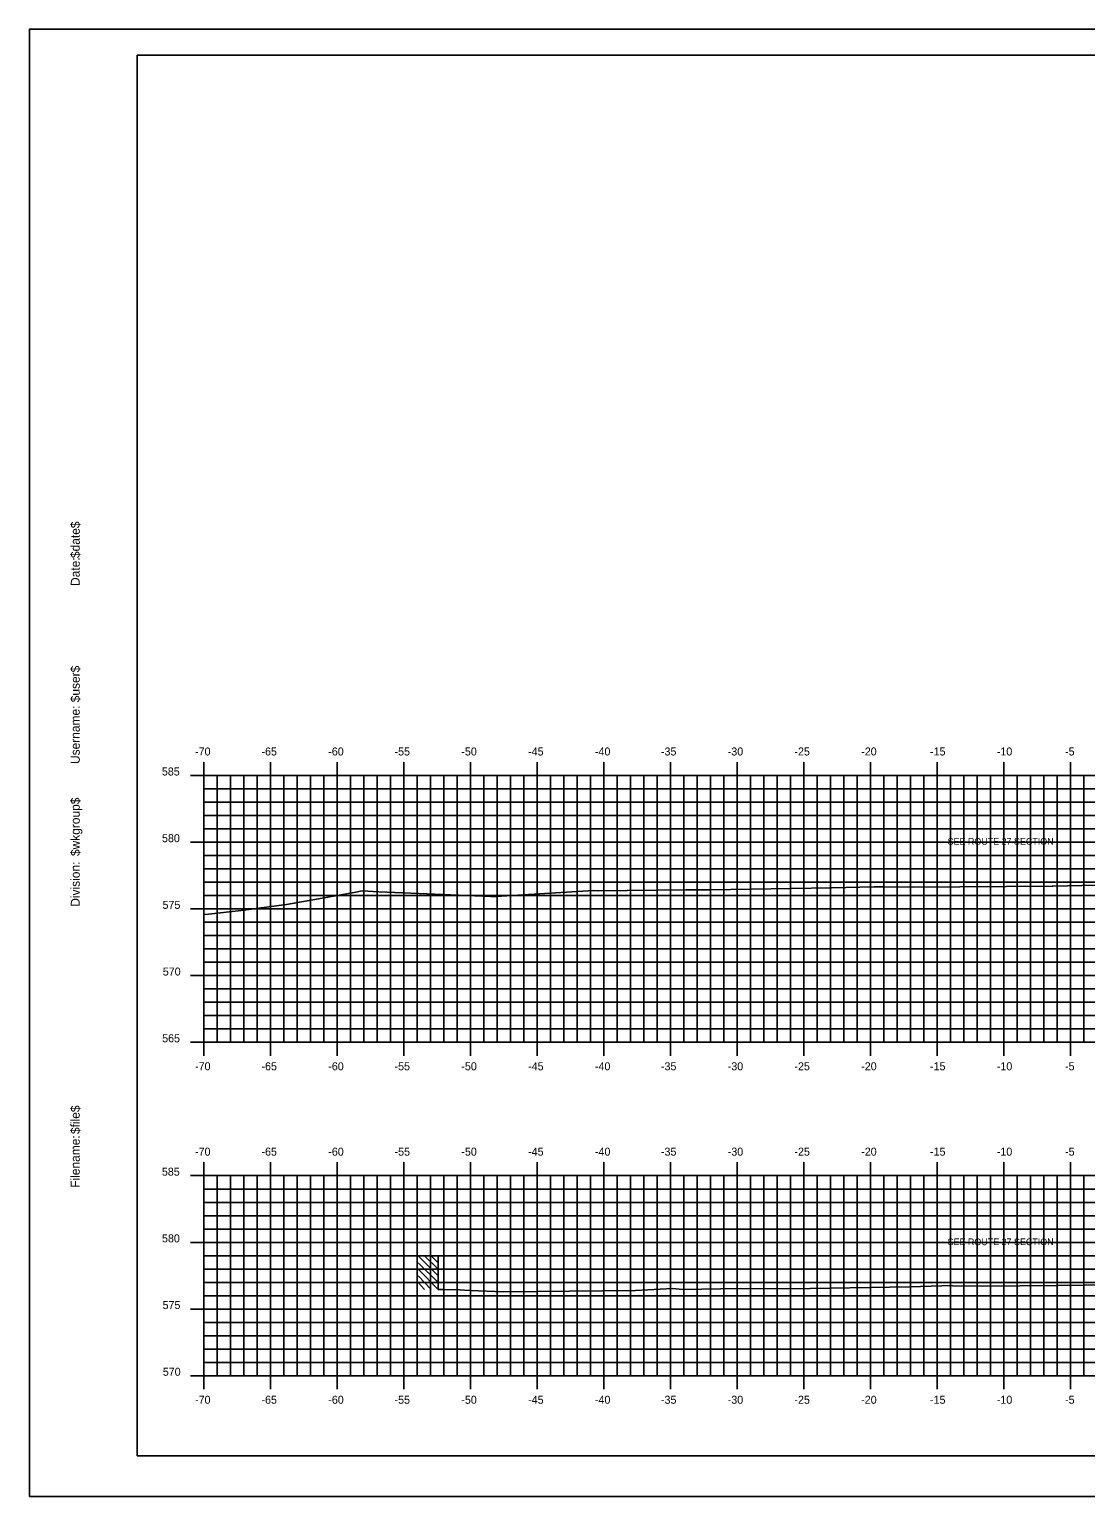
# Model space of a CAD drawing. Extents: x 1048121 to 1048291, y 781387 to 781497.
# Drawn here: x 1048121.3 to 1048200.5, y 781387.3 to 781497.3 of the extents above; entities that cross this region are included whole.
import ezdxf

# ---------------------------------------------------------------- set-up
doc = ezdxf.new("R2010")
doc.units = 0
for name, color, linetype in [('ANNOTATION', 7, 'Continuous'), ('BORDER', 7, 'Continuous'), ('H_V ANNOTATION', 7, 'Continuous'), ('MAJOR', 7, 'Continuous'), ('MINOR', 7, 'Continuous'), ('PLOT BOUNDARY', 7, 'Continuous'), ('S_Buildings', 7, 'Continuous'), ('S_Roadway_Centerline', 7, 'Continuous')]:
    doc.layers.add(name, color=color, linetype=linetype)

msp = doc.modelspace()

# ---------------------------------------------------------------- linework, layer by layer
at = {"layer": 'BORDER'}
msp.add_lwpolyline([(1048129.36, 781390.38), (1048289.36, 781390.38), (1048289.36, 781495.38), (1048129.36, 781495.38)], close=True, dxfattribs=at)
at = {"layer": 'MAJOR'}
for p, q in [((1048134.36, 781442.38), (1048134.36, 781441.38)), ((1048139.36, 781442.38), (1048139.36, 781441.38)), ((1048144.36, 781442.38), (1048144.36, 781441.38)), ((1048149.36, 781442.38), (1048149.36, 781441.38)), ((1048154.36, 781442.38), (1048154.36, 781441.38)), ((1048159.36, 781442.38), (1048159.36, 781441.38)), ((1048164.36, 781442.38), (1048164.36, 781441.38)), ((1048169.36, 781442.38), (1048169.36, 781441.38)), ((1048174.36, 781442.38), (1048174.36, 781441.38)), ((1048179.36, 781442.38), (1048179.36, 781441.38)), ((1048184.36, 781442.38), (1048184.36, 781441.38)), ((1048189.36, 781442.38), (1048189.36, 781441.38)), ((1048194.36, 781442.38), (1048194.36, 781441.38)), ((1048199.36, 781442.38), (1048199.36, 781441.38)), ((1048133.36, 781441.38), (1048134.36, 781441.38)), ((1048134.36, 781441.38), (1048274.36, 781441.38)), ((1048134.36, 781421.38), (1048134.36, 781441.38)), ((1048134.36, 781421.38), (1048134.36, 781441.38)), ((1048134.36, 781441.38), (1048274.36, 781441.38)), ((1048139.36, 781421.38), (1048139.36, 781441.38)), ((1048144.36, 781421.38), (1048144.36, 781441.38)), ((1048149.36, 781421.38), (1048149.36, 781441.38)), ((1048154.36, 781421.38), (1048154.36, 781441.38)), ((1048159.36, 781421.38), (1048159.36, 781441.38)), ((1048164.36, 781421.38), (1048164.36, 781441.38)), ((1048169.36, 781421.38), (1048169.36, 781441.38)), ((1048174.36, 781421.38), (1048174.36, 781441.38)), ((1048179.36, 781421.38), (1048179.36, 781441.38)), ((1048184.36, 781421.38), (1048184.36, 781441.38)), ((1048189.36, 781421.38), (1048189.36, 781441.38)), ((1048194.36, 781421.38), (1048194.36, 781441.38)), ((1048199.36, 781421.38), (1048199.36, 781441.38)), ((1048133.36, 781436.38), (1048134.36, 781436.38)), ((1048134.36, 781436.38), (1048274.36, 781436.38)), ((1048133.36, 781431.38), (1048134.36, 781431.38)), ((1048134.36, 781431.38), (1048274.36, 781431.38)), ((1048133.36, 781426.38), (1048134.36, 781426.38)), ((1048134.36, 781426.38), (1048274.36, 781426.38)), ((1048133.36, 781421.38), (1048134.36, 781421.38)), ((1048134.36, 781421.38), (1048274.36, 781421.38)), ((1048134.36, 781421.38), (1048274.36, 781421.38)), ((1048134.36, 781420.37), (1048134.36, 781421.38)), ((1048139.36, 781420.37), (1048139.36, 781421.38)), ((1048144.36, 781420.37), (1048144.36, 781421.38)), ((1048149.36, 781420.37), (1048149.36, 781421.38)), ((1048154.36, 781420.37), (1048154.36, 781421.38)), ((1048159.36, 781420.37), (1048159.36, 781421.38)), ((1048164.36, 781420.37), (1048164.36, 781421.38)), ((1048169.36, 781420.37), (1048169.36, 781421.38)), ((1048174.36, 781420.37), (1048174.36, 781421.38)), ((1048179.36, 781420.37), (1048179.36, 781421.38)), ((1048184.36, 781420.37), (1048184.36, 781421.38)), ((1048189.36, 781420.37), (1048189.36, 781421.38)), ((1048194.36, 781420.37), (1048194.36, 781421.38)), ((1048199.36, 781420.37), (1048199.36, 781421.38)), ((1048134.36, 781412.38), (1048134.36, 781411.38)), ((1048139.36, 781412.38), (1048139.36, 781411.38)), ((1048144.36, 781412.38), (1048144.36, 781411.38)), ((1048149.36, 781412.38), (1048149.36, 781411.38)), ((1048154.36, 781412.38), (1048154.36, 781411.38)), ((1048159.36, 781412.38), (1048159.36, 781411.38)), ((1048164.36, 781412.38), (1048164.36, 781411.38)), ((1048169.36, 781412.38), (1048169.36, 781411.38)), ((1048174.36, 781412.38), (1048174.36, 781411.38)), ((1048179.36, 781412.38), (1048179.36, 781411.38)), ((1048184.36, 781412.38), (1048184.36, 781411.38)), ((1048189.36, 781412.38), (1048189.36, 781411.38)), ((1048194.36, 781412.38), (1048194.36, 781411.38)), ((1048199.36, 781412.38), (1048199.36, 781411.38)), ((1048133.36, 781411.38), (1048134.36, 781411.38)), ((1048134.36, 781411.38), (1048274.36, 781411.38)), ((1048134.36, 781396.38), (1048134.36, 781411.38)), ((1048134.36, 781396.38), (1048134.36, 781411.38)), ((1048134.36, 781411.38), (1048274.36, 781411.38)), ((1048139.36, 781396.38), (1048139.36, 781411.38)), ((1048144.36, 781396.38), (1048144.36, 781411.38)), ((1048149.36, 781396.38), (1048149.36, 781411.38)), ((1048154.36, 781396.38), (1048154.36, 781411.38)), ((1048159.36, 781396.38), (1048159.36, 781411.38)), ((1048164.36, 781396.38), (1048164.36, 781411.38)), ((1048169.36, 781396.38), (1048169.36, 781411.38)), ((1048174.36, 781396.38), (1048174.36, 781411.38)), ((1048179.36, 781396.38), (1048179.36, 781411.38)), ((1048184.36, 781396.38), (1048184.36, 781411.38)), ((1048189.36, 781396.38), (1048189.36, 781411.38)), ((1048194.36, 781396.38), (1048194.36, 781411.38)), ((1048199.36, 781396.38), (1048199.36, 781411.38)), ((1048133.36, 781406.38), (1048134.36, 781406.38)), ((1048134.36, 781406.38), (1048274.36, 781406.38)), ((1048133.36, 781401.38), (1048134.36, 781401.38)), ((1048134.36, 781401.38), (1048274.36, 781401.38)), ((1048133.36, 781396.38), (1048134.36, 781396.38)), ((1048134.36, 781396.38), (1048274.36, 781396.38)), ((1048134.36, 781396.38), (1048274.36, 781396.38)), ((1048134.36, 781395.37), (1048134.36, 781396.38)), ((1048139.36, 781395.37), (1048139.36, 781396.38)), ((1048144.36, 781395.37), (1048144.36, 781396.38)), ((1048149.36, 781395.37), (1048149.36, 781396.38)), ((1048154.36, 781395.37), (1048154.36, 781396.38)), ((1048159.36, 781395.37), (1048159.36, 781396.38)), ((1048164.36, 781395.37), (1048164.36, 781396.38)), ((1048169.36, 781395.37), (1048169.36, 781396.38)), ((1048174.36, 781395.37), (1048174.36, 781396.38)), ((1048179.36, 781395.37), (1048179.36, 781396.38)), ((1048184.36, 781395.37), (1048184.36, 781396.38)), ((1048189.36, 781395.37), (1048189.36, 781396.38)), ((1048194.36, 781395.37), (1048194.36, 781396.38)), ((1048199.36, 781395.37), (1048199.36, 781396.38))]:
    msp.add_line(p, q, dxfattribs=at)
at = {"layer": 'MINOR'}
for p, q in [((1048135.36, 781421.38), (1048135.36, 781441.38)), ((1048136.36, 781421.38), (1048136.36, 781441.38)), ((1048137.36, 781421.38), (1048137.36, 781441.38)), ((1048138.36, 781421.38), (1048138.36, 781441.38)), ((1048140.36, 781421.38), (1048140.36, 781441.38)), ((1048141.36, 781421.38), (1048141.36, 781441.38)), ((1048142.36, 781421.38), (1048142.36, 781441.38)), ((1048143.36, 781421.38), (1048143.36, 781441.38)), ((1048145.36, 781421.38), (1048145.36, 781441.38)), ((1048146.36, 781421.38), (1048146.36, 781441.38)), ((1048147.36, 781421.38), (1048147.36, 781441.38)), ((1048148.36, 781421.38), (1048148.36, 781441.38)), ((1048150.36, 781421.38), (1048150.36, 781441.38)), ((1048151.36, 781421.38), (1048151.36, 781441.38)), ((1048152.36, 781421.38), (1048152.36, 781441.38)), ((1048153.36, 781421.38), (1048153.36, 781441.38)), ((1048155.36, 781421.38), (1048155.36, 781441.38)), ((1048156.36, 781421.38), (1048156.36, 781441.38)), ((1048157.36, 781421.38), (1048157.36, 781441.38)), ((1048158.36, 781421.38), (1048158.36, 781441.38)), ((1048160.36, 781421.38), (1048160.36, 781441.38)), ((1048161.36, 781421.38), (1048161.36, 781441.38)), ((1048162.36, 781421.38), (1048162.36, 781441.38)), ((1048163.36, 781421.38), (1048163.36, 781441.38)), ((1048165.36, 781421.38), (1048165.36, 781441.38)), ((1048166.36, 781421.38), (1048166.36, 781441.38)), ((1048167.36, 781421.38), (1048167.36, 781441.38)), ((1048168.36, 781421.38), (1048168.36, 781441.38)), ((1048170.36, 781421.38), (1048170.36, 781441.38)), ((1048171.36, 781421.38), (1048171.36, 781441.38)), ((1048172.36, 781421.38), (1048172.36, 781441.38)), ((1048173.36, 781421.38), (1048173.36, 781441.38)), ((1048175.36, 781421.38), (1048175.36, 781441.38)), ((1048176.36, 781421.38), (1048176.36, 781441.38)), ((1048177.36, 781421.38), (1048177.36, 781441.38)), ((1048178.36, 781421.38), (1048178.36, 781441.38)), ((1048180.36, 781421.38), (1048180.36, 781441.38)), ((1048181.36, 781421.38), (1048181.36, 781441.38)), ((1048182.36, 781421.38), (1048182.36, 781441.38)), ((1048183.36, 781421.38), (1048183.36, 781441.38)), ((1048185.36, 781421.38), (1048185.36, 781441.38)), ((1048186.36, 781421.38), (1048186.36, 781441.38)), ((1048187.36, 781421.38), (1048187.36, 781441.38)), ((1048188.36, 781421.38), (1048188.36, 781441.38)), ((1048190.36, 781421.38), (1048190.36, 781441.38)), ((1048191.36, 781421.38), (1048191.36, 781441.38)), ((1048192.36, 781421.38), (1048192.36, 781441.38)), ((1048193.36, 781421.38), (1048193.36, 781441.38)), ((1048195.36, 781421.38), (1048195.36, 781441.38)), ((1048196.36, 781421.38), (1048196.36, 781441.38)), ((1048197.36, 781421.38), (1048197.36, 781441.38)), ((1048198.36, 781421.38), (1048198.36, 781441.38)), ((1048200.36, 781421.38), (1048200.36, 781441.38)), ((1048134.36, 781440.38), (1048274.36, 781440.38)), ((1048134.36, 781440.38), (1048135.36, 781440.38)), ((1048134.36, 781439.38), (1048274.36, 781439.38)), ((1048134.36, 781439.38), (1048135.36, 781439.38)), ((1048134.36, 781438.38), (1048274.36, 781438.38)), ((1048134.36, 781438.38), (1048135.36, 781438.38)), ((1048134.36, 781437.38), (1048274.36, 781437.38)), ((1048134.36, 781437.38), (1048135.36, 781437.38)), ((1048134.36, 781435.38), (1048274.36, 781435.38)), ((1048134.36, 781435.38), (1048135.36, 781435.38)), ((1048134.36, 781434.38), (1048274.36, 781434.38)), ((1048134.36, 781434.38), (1048135.36, 781434.38)), ((1048134.36, 781433.38), (1048274.36, 781433.38)), ((1048134.36, 781433.38), (1048135.36, 781433.38)), ((1048134.36, 781432.38), (1048274.36, 781432.38)), ((1048134.36, 781432.38), (1048135.36, 781432.38)), ((1048134.36, 781430.38), (1048274.36, 781430.38)), ((1048134.36, 781430.38), (1048135.36, 781430.38)), ((1048134.36, 781429.38), (1048274.36, 781429.38)), ((1048134.36, 781429.38), (1048135.36, 781429.38)), ((1048134.36, 781428.38), (1048274.36, 781428.38)), ((1048134.36, 781428.38), (1048135.36, 781428.38)), ((1048134.36, 781427.38), (1048274.36, 781427.38)), ((1048134.36, 781427.38), (1048135.36, 781427.38)), ((1048134.36, 781425.38), (1048274.36, 781425.38)), ((1048134.36, 781425.38), (1048135.36, 781425.38)), ((1048134.36, 781424.38), (1048274.36, 781424.38)), ((1048134.36, 781424.38), (1048135.36, 781424.38)), ((1048134.36, 781423.38), (1048274.36, 781423.38)), ((1048134.36, 781423.38), (1048135.36, 781423.38)), ((1048134.36, 781422.38), (1048274.36, 781422.38)), ((1048134.36, 781422.38), (1048135.36, 781422.38)), ((1048134.36, 781410.38), (1048274.36, 781410.38)), ((1048134.36, 781410.38), (1048135.36, 781410.38)), ((1048135.36, 781396.38), (1048135.36, 781411.38)), ((1048136.36, 781396.38), (1048136.36, 781411.38)), ((1048137.36, 781396.38), (1048137.36, 781411.38)), ((1048138.36, 781396.38), (1048138.36, 781411.38)), ((1048140.36, 781396.38), (1048140.36, 781411.38)), ((1048141.36, 781396.38), (1048141.36, 781411.38)), ((1048142.36, 781396.38), (1048142.36, 781411.38)), ((1048143.36, 781396.38), (1048143.36, 781411.38)), ((1048145.36, 781396.38), (1048145.36, 781411.38)), ((1048146.36, 781396.38), (1048146.36, 781411.38)), ((1048147.36, 781396.38), (1048147.36, 781411.38)), ((1048148.36, 781396.38), (1048148.36, 781411.38)), ((1048150.36, 781396.38), (1048150.36, 781411.38)), ((1048151.36, 781396.38), (1048151.36, 781411.38)), ((1048152.36, 781396.38), (1048152.36, 781411.38)), ((1048153.36, 781396.38), (1048153.36, 781411.38)), ((1048155.36, 781396.38), (1048155.36, 781411.38)), ((1048156.36, 781396.38), (1048156.36, 781411.38)), ((1048157.36, 781396.38), (1048157.36, 781411.38)), ((1048158.36, 781396.38), (1048158.36, 781411.38)), ((1048160.36, 781396.38), (1048160.36, 781411.38)), ((1048161.36, 781396.38), (1048161.36, 781411.38)), ((1048162.36, 781396.38), (1048162.36, 781411.38)), ((1048163.36, 781396.38), (1048163.36, 781411.38)), ((1048165.36, 781396.38), (1048165.36, 781411.38)), ((1048166.36, 781396.38), (1048166.36, 781411.38)), ((1048167.36, 781396.38), (1048167.36, 781411.38)), ((1048168.36, 781396.38), (1048168.36, 781411.38)), ((1048170.36, 781396.38), (1048170.36, 781411.38)), ((1048171.36, 781396.38), (1048171.36, 781411.38)), ((1048172.36, 781396.38), (1048172.36, 781411.38)), ((1048173.36, 781396.38), (1048173.36, 781411.38)), ((1048175.36, 781396.38), (1048175.36, 781411.38)), ((1048176.36, 781396.38), (1048176.36, 781411.38)), ((1048177.36, 781396.38), (1048177.36, 781411.38)), ((1048178.36, 781396.38), (1048178.36, 781411.38)), ((1048180.36, 781396.38), (1048180.36, 781411.38)), ((1048181.36, 781396.38), (1048181.36, 781411.38)), ((1048182.36, 781396.38), (1048182.36, 781411.38)), ((1048183.36, 781396.38), (1048183.36, 781411.38)), ((1048185.36, 781396.38), (1048185.36, 781411.38)), ((1048186.36, 781396.38), (1048186.36, 781411.38)), ((1048187.36, 781396.38), (1048187.36, 781411.38)), ((1048188.36, 781396.38), (1048188.36, 781411.38)), ((1048190.36, 781396.38), (1048190.36, 781411.38)), ((1048191.36, 781396.38), (1048191.36, 781411.38)), ((1048192.36, 781396.38), (1048192.36, 781411.38)), ((1048193.36, 781396.38), (1048193.36, 781411.38)), ((1048195.36, 781396.38), (1048195.36, 781411.38)), ((1048196.36, 781396.38), (1048196.36, 781411.38)), ((1048197.36, 781396.38), (1048197.36, 781411.38)), ((1048198.36, 781396.38), (1048198.36, 781411.38)), ((1048200.36, 781396.38), (1048200.36, 781411.38)), ((1048134.36, 781409.38), (1048274.36, 781409.38)), ((1048134.36, 781409.38), (1048135.36, 781409.38)), ((1048134.36, 781408.38), (1048274.36, 781408.38)), ((1048134.36, 781408.38), (1048135.36, 781408.38)), ((1048134.36, 781407.38), (1048274.36, 781407.38)), ((1048134.36, 781407.38), (1048135.36, 781407.38)), ((1048134.36, 781405.38), (1048274.36, 781405.38)), ((1048134.36, 781405.38), (1048135.36, 781405.38)), ((1048134.36, 781404.38), (1048274.36, 781404.38)), ((1048134.36, 781404.38), (1048135.36, 781404.38)), ((1048134.36, 781403.38), (1048274.36, 781403.38)), ((1048134.36, 781403.38), (1048135.36, 781403.38)), ((1048134.36, 781402.38), (1048274.36, 781402.38)), ((1048134.36, 781402.38), (1048135.36, 781402.38)), ((1048134.36, 781400.38), (1048274.36, 781400.38)), ((1048134.36, 781400.38), (1048135.36, 781400.38)), ((1048134.36, 781399.38), (1048274.36, 781399.38)), ((1048134.36, 781399.38), (1048135.36, 781399.38)), ((1048134.36, 781398.38), (1048274.36, 781398.38)), ((1048134.36, 781398.38), (1048135.36, 781398.38)), ((1048134.36, 781397.38), (1048274.36, 781397.38)), ((1048134.36, 781397.38), (1048135.36, 781397.38))]:
    msp.add_line(p, q, dxfattribs=at)
at = {"layer": 'PLOT BOUNDARY'}
msp.add_lwpolyline([(1048121.27, 781387.32), (1048291.27, 781387.32), (1048291.27, 781497.32), (1048121.27, 781497.32)], close=True, dxfattribs=at)
at = {"layer": 'S_Buildings'}
for p, q in [((1048151.92, 781403.87), (1048150.42, 781405.38)), ((1048151.92, 781403.37), (1048150.42, 781404.85)), ((1048151.92, 781404.36), (1048150.91, 781405.38)), ((1048151.92, 781404.85), (1048151.4, 781405.38)), ((1048151.92, 781402.85), (1048151.92, 781405.38)), ((1048151.92, 781402.85), (1048150.42, 781404.36)), ((1048151.4, 781402.85), (1048150.42, 781403.87)), ((1048150.91, 781402.85), (1048150.42, 781403.37))]:
    msp.add_line(p, q, dxfattribs=at)
at = {"layer": 'S_Roadway_Centerline'}
for points in [[(1048134.36, 781430.97), (1048134.7, 781430.98), (1048137.16, 781431.27), (1048140.56, 781431.72), (1048145.62, 781432.61), (1048146.23, 781432.73), (1048147.47, 781432.67), (1048155.89, 781432.31), (1048156.27, 781432.31), (1048163.59, 781432.76), (1048163.91, 781432.73), (1048163.91, 781432.73), (1048170.51, 781432.81), (1048172.36, 781432.81), (1048181.44, 781432.96), (1048184.62, 781433.03), (1048185.37, 781433.03), (1048187.6, 781433.02), (1048187.61, 781433.02), (1048197.97, 781433.08), (1048198.04, 781433.09), (1048204.6, 781433.23)], [(1048151.92, 781402.85), (1048152.4, 781402.84), (1048153.53, 781402.82), (1048154.31, 781402.78), (1048156.82, 781402.67), (1048166.73, 781402.76), (1048169.51, 781402.93), (1048170.26, 781402.85), (1048170.26, 781402.85), (1048174.58, 781402.91), (1048178.34, 781402.9), (1048187.3, 781403.05), (1048190.5, 781403.14), (1048190.51, 781403.12), (1048192.74, 781403.09), (1048198.39, 781403.15), (1048202.27, 781403.19)]]:
    msp.add_lwpolyline(points, dxfattribs=at)

# ---------------------------------------------------------------- texts
at = {"layer": 'ANNOTATION'}
for p in [(1048190.14, 781436.19), (1048190.14, 781406.17)]:
    msp.add_text('SEE ROUTE 27 SECTION', height=0.5, dxfattribs=at).set_placement(p)
at = {"layer": 'BORDER'}
for s, p in [('$date$', (1048125.05, 781457.68)), ('Date:', (1048125.05, 781455.59)), ('$user$', (1048125.05, 781446.87)), ('Username:', (1048125.05, 781442.24)), ('$wkgroup$', (1048125.05, 781435.34)), ('Division:', (1048125.05, 781431.54)), ('$file$', (1048125.05, 781414.5)), ('Filename:', (1048125.05, 781410.47))]:
    msp.add_text(s, height=0.67, rotation=90, dxfattribs=at).set_placement(p)
at = {"layer": 'H_V ANNOTATION'}
for s, p in [('-70', (1048133.7, 781442.88)), ('-65', (1048138.68, 781442.88)), ('-60', (1048143.69, 781442.88)), ('-55', (1048148.66, 781442.88)), ('-50', (1048153.67, 781442.88)), ('-45', (1048158.68, 781442.88)), ('-40', (1048163.69, 781442.88)), ('-35', (1048168.64, 781442.88)), ('-30', (1048173.65, 781442.88)), ('-25', (1048178.65, 781442.88)), ('-20', (1048183.66, 781442.88)), ('-15', (1048188.82, 781442.88)), ('-10', (1048193.83, 781442.88)), ('-5', (1048198.95, 781442.88)), ('585', (1048131.21, 781441.38)), ('580', (1048131.22, 781436.38)), ('575', (1048131.26, 781431.38)), ('570', (1048131.28, 781426.38)), ('565', (1048131.23, 781421.38)), ('-70', (1048133.7, 781419.28)), ('-65', (1048138.68, 781419.28)), ('-60', (1048143.69, 781419.28)), ('-55', (1048148.66, 781419.28)), ('-50', (1048153.67, 781419.28)), ('-45', (1048158.68, 781419.28)), ('-40', (1048163.69, 781419.28)), ('-35', (1048168.64, 781419.28)), ('-30', (1048173.65, 781419.28)), ('-25', (1048178.65, 781419.28)), ('-20', (1048183.66, 781419.28)), ('-15', (1048188.82, 781419.28)), ('-10', (1048193.83, 781419.28)), ('-5', (1048198.95, 781419.28)), ('-70', (1048133.7, 781412.88)), ('-65', (1048138.68, 781412.88)), ('-60', (1048143.69, 781412.88)), ('-55', (1048148.66, 781412.88)), ('-50', (1048153.67, 781412.88)), ('-45', (1048158.68, 781412.88)), ('-40', (1048163.69, 781412.88)), ('-35', (1048168.64, 781412.88)), ('-30', (1048173.65, 781412.88)), ('-25', (1048178.65, 781412.88)), ('-20', (1048183.66, 781412.88)), ('-15', (1048188.82, 781412.88)), ('-10', (1048193.83, 781412.88)), ('-5', (1048198.95, 781412.88)), ('585', (1048131.21, 781411.38)), ('580', (1048131.22, 781406.38)), ('575', (1048131.26, 781401.38)), ('570', (1048131.28, 781396.38)), ('-70', (1048133.7, 781394.28)), ('-65', (1048138.68, 781394.28)), ('-60', (1048143.69, 781394.28)), ('-55', (1048148.66, 781394.28)), ('-50', (1048153.67, 781394.28)), ('-45', (1048158.68, 781394.28)), ('-40', (1048163.69, 781394.28)), ('-35', (1048168.64, 781394.28)), ('-30', (1048173.65, 781394.28)), ('-25', (1048178.65, 781394.28)), ('-20', (1048183.66, 781394.28)), ('-15', (1048188.82, 781394.28)), ('-10', (1048193.83, 781394.28)), ('-5', (1048198.95, 781394.28))]:
    msp.add_text(s, height=0.6, dxfattribs=at).set_placement(p)
at = {"layer": 'MAJOR'}
for p in [(1048134.36, 781421.38), (1048134.36, 781396.38)]:
    msp.add_text('-', height=0.006, dxfattribs=at).set_placement(p)
at = {"layer": 'S_Roadway_Centerline'}
for s, p in [('L', (1048184.61, 781433.02)), ('C', (1048184.61, 781433.03)), ('C', (1048190.5, 781403.14)), ('L', (1048190.5, 781403.13))]:
    msp.add_text(s, height=0.0146, dxfattribs=at).set_placement(p)

doc.saveas('drawing.dxf')
